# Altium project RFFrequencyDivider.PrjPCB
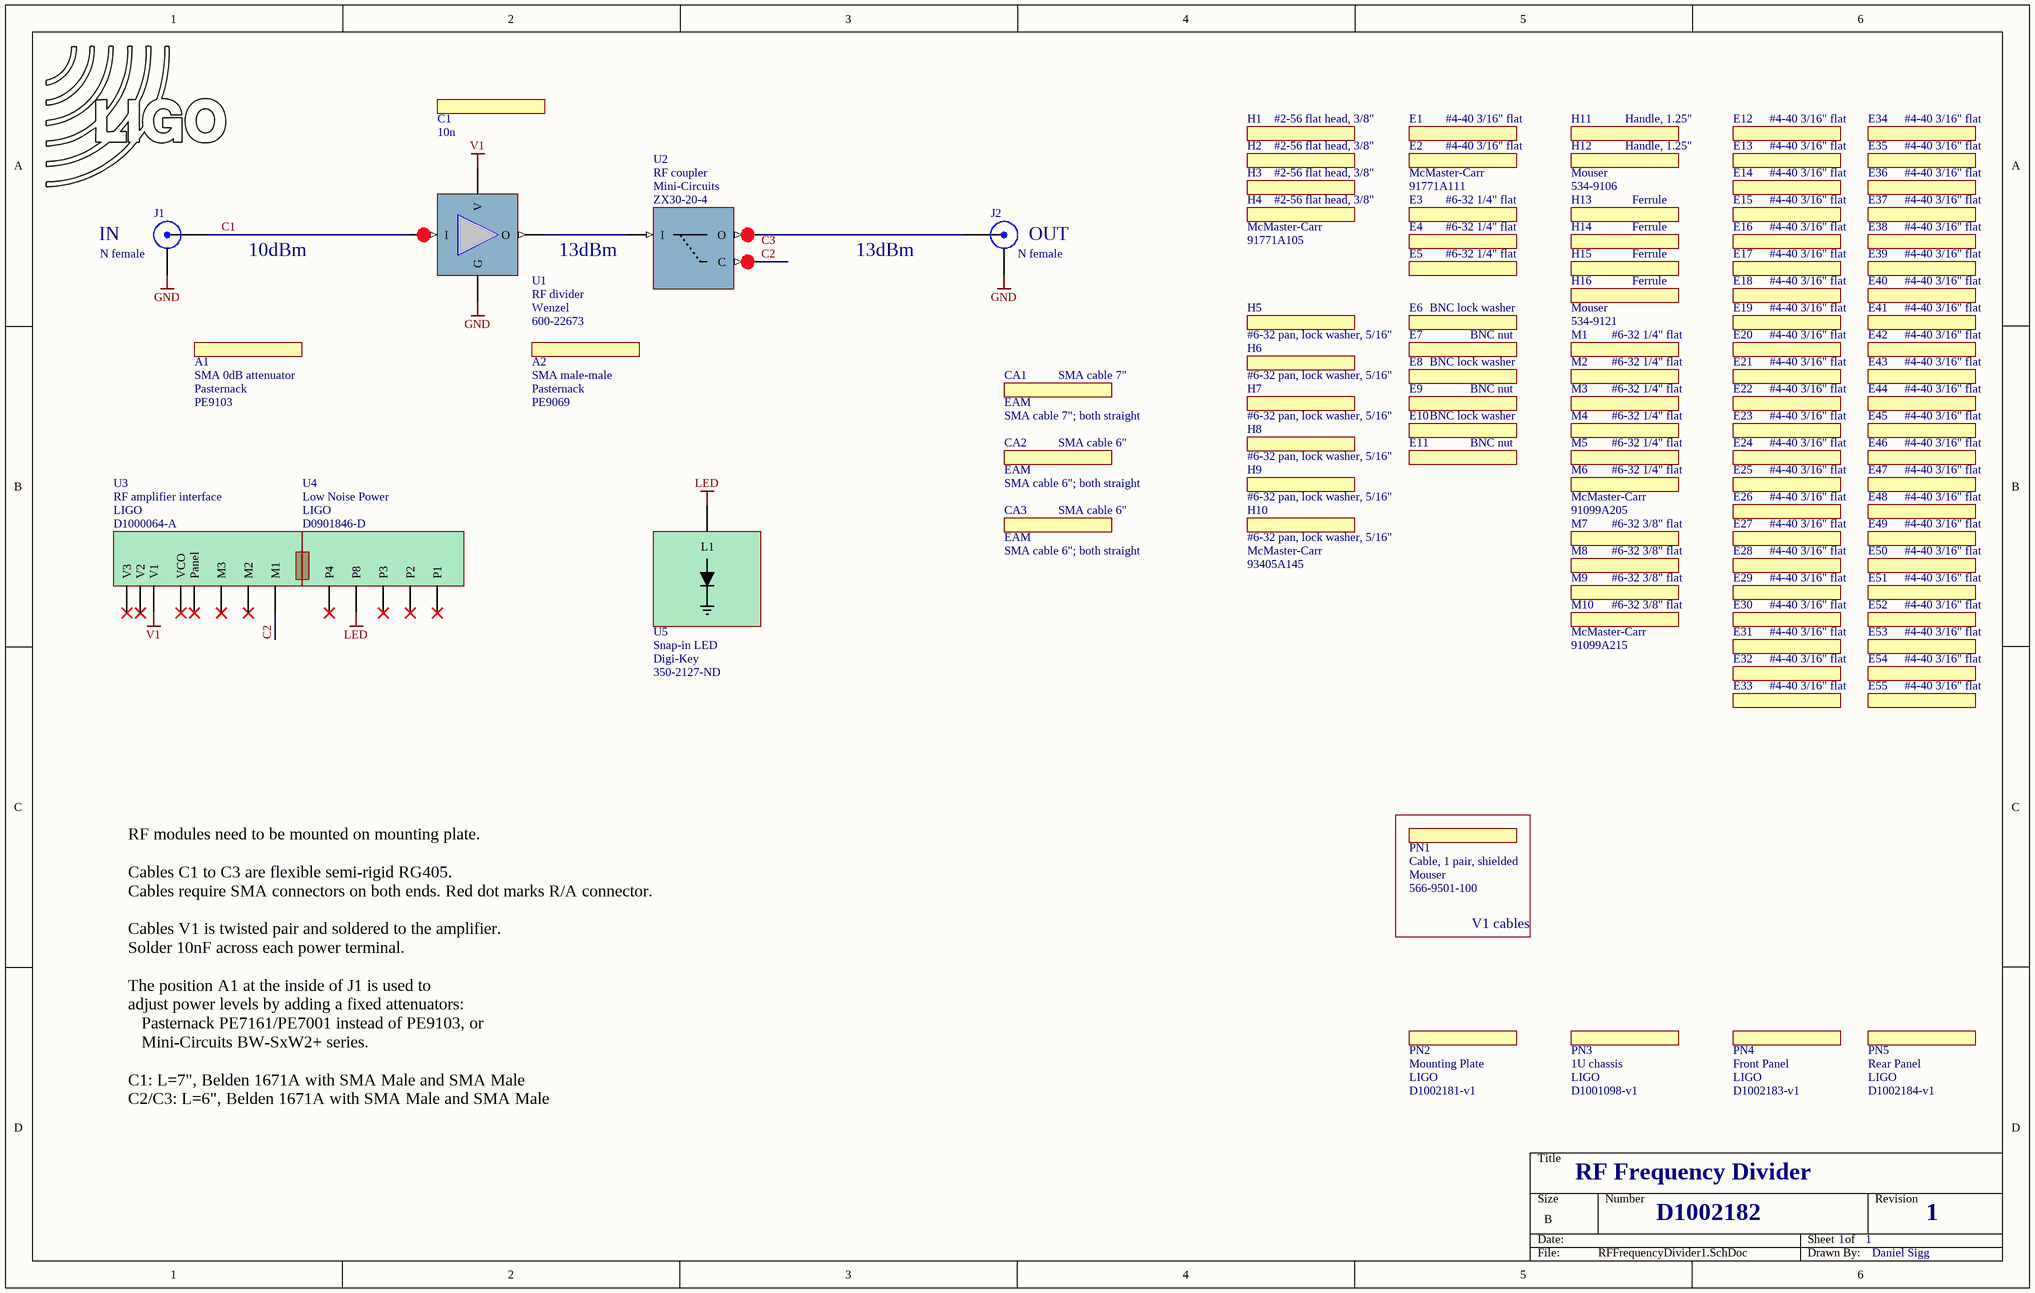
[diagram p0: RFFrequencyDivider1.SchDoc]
1 sheet, 100 parts. Net scope: global (net labels, ports and power ports of the same name join across sheets).

## Sheet RFFrequencyDivider1.SchDoc: D1000124
size B; Engineer: Daniel Sigg; Revision: 1; PageSetup: Record=PageOptions|CenterHorizontal=True|CenterVertical=True|PrintScale=1.12|XCorrection=1.00|YCorrection=1.00|PrintKind=0|BorderSize=5000000|LeftOffset=0|BottomOffset=0|Orientation=2|PaperLength=1000|PaperWidth=1000|Scale=100|PaperSource=7|PrintQuality=-4|MediaType=1|DitherType=10|PaperKind=11 x 17|PrintScaleMode=1

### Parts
A1  SMA 0dB attenuator  Part Number: PE9103  Distributor: Pasternack  (graphical)
A2  SMA male-male  Part Number: PE9069  Distributor: Pasternack
C1  10n  (mechanical)
CA1  SMA cable 7"  Part Number: SMA cable 7"; both straight  Distributor: EAM  (mechanical)
CA2  SMA cable 6"  Part Number: SMA cable 6"; both straight  Distributor: EAM  (mechanical)
CA3  SMA cable 6"  Part Number: SMA cable 6"; both straight  Distributor: EAM  (mechanical)
E1  #4-40 3/16" flat  (mechanical)
E2  #4-40 3/16" flat  Part Number: 91771A111  Distributor: McMaster-Carr  (mechanical)
E3  #6-32 1/4" flat  (mechanical)
E4  #6-32 1/4" flat  (mechanical)
E5  #6-32 1/4" flat  (mechanical)
E6  BNC lock washer  (mechanical)
E7  BNC nut  (mechanical)
E8  BNC lock washer  (mechanical)
E9  BNC nut  (mechanical)
E10  BNC lock washer  (mechanical)
E11  BNC nut  (mechanical)
E12  #4-40 3/16" flat  (mechanical)
E13  #4-40 3/16" flat  (mechanical)
E14  #4-40 3/16" flat  (mechanical)
E15  #4-40 3/16" flat  (mechanical)
E16  #4-40 3/16" flat  (mechanical)
E17  #4-40 3/16" flat  (mechanical)
E18  #4-40 3/16" flat  (mechanical)
E19  #4-40 3/16" flat  (mechanical)
E20  #4-40 3/16" flat  (mechanical)
E21  #4-40 3/16" flat  (mechanical)
E22  #4-40 3/16" flat  (mechanical)
E23  #4-40 3/16" flat  (mechanical)
E24  #4-40 3/16" flat  (mechanical)
E25  #4-40 3/16" flat  (mechanical)
E26  #4-40 3/16" flat  (mechanical)
E27  #4-40 3/16" flat  (mechanical)
E28  #4-40 3/16" flat  (mechanical)
E29  #4-40 3/16" flat  (mechanical)
E30  #4-40 3/16" flat  (mechanical)
E31  #4-40 3/16" flat  (mechanical)
E32  #4-40 3/16" flat  (mechanical)
E33  #4-40 3/16" flat  (mechanical)
E34  #4-40 3/16" flat  (mechanical)
E35  #4-40 3/16" flat  (mechanical)
E36  #4-40 3/16" flat  (mechanical)
E37  #4-40 3/16" flat  (mechanical)
E38  #4-40 3/16" flat  (mechanical)
E39  #4-40 3/16" flat  (mechanical)
E40  #4-40 3/16" flat  (mechanical)
E41  #4-40 3/16" flat  (mechanical)
E42  #4-40 3/16" flat  (mechanical)
E43  #4-40 3/16" flat  (mechanical)
E44  #4-40 3/16" flat  (mechanical)
E45  #4-40 3/16" flat  (mechanical)
E46  #4-40 3/16" flat  (mechanical)
E47  #4-40 3/16" flat  (mechanical)
E48  #4-40 3/16" flat  (mechanical)
E49  #4-40 3/16" flat  (mechanical)
E50  #4-40 3/16" flat  (mechanical)
E51  #4-40 3/16" flat  (mechanical)
E52  #4-40 3/16" flat  (mechanical)
E53  #4-40 3/16" flat  (mechanical)
E54  #4-40 3/16" flat  (mechanical)
E55  #4-40 3/16" flat  (mechanical)
H1  #2-56 flat head, 3/8"  (mechanical)
H2  #2-56 flat head, 3/8"  (mechanical)
H3  #2-56 flat head, 3/8"  (mechanical)
H4  #2-56 flat head, 3/8"  Part Number: 91771A105  Distributor: McMaster-Carr  (mechanical)
H5  #6-32 pan, lock washer, 5/16"  (mechanical)
H6  #6-32 pan, lock washer, 5/16"  (mechanical)
H7  #6-32 pan, lock washer, 5/16"  (mechanical)
H8  #6-32 pan, lock washer, 5/16"  (mechanical)
H9  #6-32 pan, lock washer, 5/16"  (mechanical)
H10  #6-32 pan, lock washer, 5/16"  Part Number: 93405A145  Distributor: McMaster-Carr  (mechanical)
H11  Handle, 1.25"  (mechanical)
H12  Handle, 1.25"  Part Number: 534-9106  Distributor: Mouser  (mechanical)
H13  Ferrule  (mechanical)
H14  Ferrule  (mechanical)
H15  Ferrule  (mechanical)
H16  Ferrule  Part Number: 534-9121  Distributor: Mouser  (mechanical)
J1  N female  [BNC1]
J2  N female  [BNC1]
LOGO1  LIGO logo  [LIGO_LOGO]  (value not drawn)  (no BOM)
M1  #6-32 1/4" flat  (mechanical)
M2  #6-32 1/4" flat  (mechanical)
M3  #6-32 1/4" flat  (mechanical)
M4  #6-32 1/4" flat  (mechanical)
M5  #6-32 1/4" flat  (mechanical)
M6  #6-32 1/4" flat  Part Number: 91099A205  Distributor: McMaster-Carr  (mechanical)
M7  #6-32 3/8" flat  (mechanical)
M8  #6-32 3/8" flat  (mechanical)
M9  #6-32 3/8" flat  (mechanical)
M10  #6-32 3/8" flat  Part Number: 91099A215  Distributor: McMaster-Carr  (mechanical)
PN1  Cable, 1 pair, shielded  Part Number: 566-9501-100  Distributor: Mouser  (mechanical)
PN2  Mounting Plate  Part Number: D1002181-v1  Distributor: LIGO  (mechanical)
PN3  1U chassis  Part Number: D1001098-v1  Distributor: LIGO  (mechanical)
PN4  Front Panel  Part Number: D1002183-v1  Distributor: LIGO  (mechanical)
PN5  Rear Panel  Part Number: D1002184-v1  Distributor: LIGO  (mechanical)
U1  RF divider  Distributor: Wenzel  Part Number: 600-22673
U2  RF coupler  Distributor: Mini-Circuits  Part Number: ZX30-20-4
U3  RF amplifier interface  Distributor: LIGO  Part Number: D1000064-A
U4  Low Noise Power  Distributor: LIGO  Part Number: D0901846-D
U5  Snap-in LED  Distributor: Digi-Key  Part Number: 350-2127-ND

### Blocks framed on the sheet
V1 cables: PN1

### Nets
GND: J1.2(Y) J2.2(Y) U1.3(G)
LED: U4.4(P8) U5.1(Panel)
V1: U1.2(V) U3.5(VCO)
C1: J1.1(X) U1.0(I)
C2: U2.2(C) U3.1(M1)
NetJ2_1: J2.1(X) U2.1(O)
NetU1_1: U1.1(O) U2.0(I)

Not connected (* = marked no-connect by the designer): U3 2(M2)* 3(M3)* 4(Panel)* 6(V2)* 7(V3)*; U4 1(P1)* 2(P2)* 3(P3)* 5(P4)*

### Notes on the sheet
- (near J1) IN
- 10dBm
- 13dBm
- (near J2) OUT
- RF modules need to be mounted on mounting plate.
  Cables C1 to C3 are flexible semi-rigid RG405.
  Cables require SMA connectors on both ends. Red dot marks R/A connector.
  Cables V1 is twisted pair and soldered to the amplifier.
  Solder 10nF across each power terminal.
  The position A1 at the inside of J1 is used to
  adjust power levels by adding a fixed attenuators:
  Pasternack PE7161/PE7001 instead of PE9103, or
  Mini-Circuits BW-SxW2+ series.
  C1: L=7", Belden 1671A with SMA Male and SMA Male
  C2/C3: L=6", Belden 1671A with SMA Male and SMA Male
- RF Frequency Divider
- D1002182
- 1
- Daniel Sigg
- Labels drawn without touching a wire or pin: C3

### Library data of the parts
A1 = Partlist: SMA female-male adapter
A2 = Partlist: SMA male-male adapter
C1 = Partlist: Capacitor; Part Number: P4948-ND
CA1-CA3 = Partlist: Belden 1671A, L=8", SMA-SMA R/A
E1 E12-E55 = Partlist: #4-40 3/16" flat head screw; Part Number: 91771A111
E2 = Partlist: #4-40 3/16" flat head screw
E3-E5 M1-M5 = Partlist: #6-32 1/4" flat head screw; Part Number: 91099A205
E6 E8 E10 = Partlist: Part Number: A97567-ND
E7 E9 E11 = Partlist: Part Number: A97566-ND
H1-H3 = Partlist: #2-56 flat head screw, 3/8"; Part Number: 91771A105
H4 = Partlist: #2-56 flat head screw, 3/8"
H5-H9 = Partlist: #6-32 pan head screw with lock washer, 5/16"; Part Number: 93405A145
H10 = Partlist: #6-32 pan head screw with lock washer, 5/16"
H11 = Partlist: Rack handle 2U; Part Number: 534-9106
H12 = Partlist: Rack handle 2U
H13-H15 = Partlist: Part Number: 534-9121
H16 = Partlist
J1 J2 = BNC: N-to-SMA bulkhead; Part Number: ACX1345-ND
LOGO1 = LIGO_logo
M6 = Partlist: #6-32 1/4" flat head screw
M7-M9 = Partlist: #6-32 3/8" flat head screw; Part Number: 91099A215
M10 = Partlist: #6-32 3/8" flat head screw
PN1 = Partlist: Cable
PN2 PN4 PN5 = Partlist: panel
PN3 = Partlist: chassis
U1 = RFAmplifier: RF amplifier
U2 = RFCoupler
U3 = RFAmplifierInterface
U4 = LowNoisePower: Low Noise Power Board
U5 = RFAmplifierLED: RF amplifier LED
